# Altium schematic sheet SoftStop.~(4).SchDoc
size A
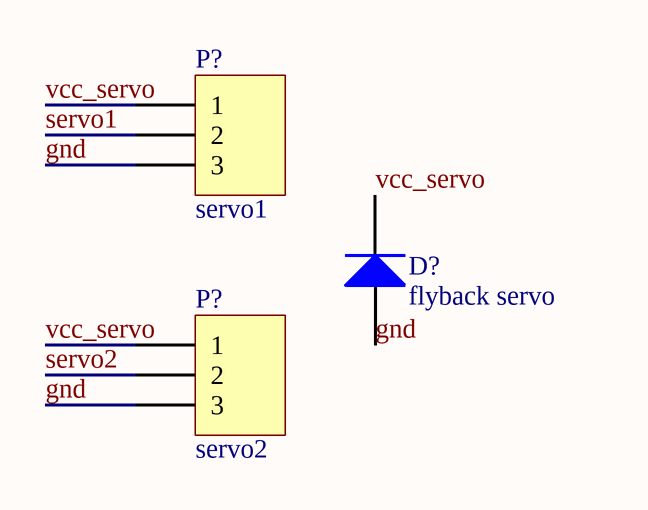
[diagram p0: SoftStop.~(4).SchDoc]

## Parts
(Parts that share a designator on the sheet are numbered #1, #2 ... from top to bottom, then left to right.)
D?  flyback servo  [DO-41]
P?#1  servo1  [HDR1X3H]
P?#2  servo2  [HDR1X3H]

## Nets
gnd: D?.1(A) P?#1.3 P?#2.3
servo1: P?#1.2
servo2: P?#2.2
vcc_servo: D?.2(K) P?#1.1 P?#2.1

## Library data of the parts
D? = Diode 1N4001: 1 Amp General Purpose Rectifier
P?#1 P?#2 = Header 3H: Header, 3-Pin, Right Angle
